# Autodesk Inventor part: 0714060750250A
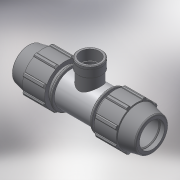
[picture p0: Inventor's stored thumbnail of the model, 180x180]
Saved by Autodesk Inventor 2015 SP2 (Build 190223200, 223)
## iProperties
Created: 2017-02
Part Number: 0714060750250A
Material: Generic
Description: PLASSON TEE WITH THREADED FEMALE OFFTAKE 75-2.1/2"-75
Document SubType Name: Modeling
Designer: KIM
Mass: 92.6774 g
Surface Area: 199.44 cm^2
Volume: 66.1981 cm^3
Density: 1 g/cm^3
Appearance: Default
Author: KIM
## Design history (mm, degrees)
derived "87140.ipt"
feature "Solid1::87140.ipt"
feature "Solid2::87140.ipt"
tag "TaggingFeature1"
body "Solid1"
other parameters: "d2" = 75, "d4" = 13.79167, "d5" = 39.72, "d7" = 134, "d11" = 5.51667, "d13" = 120 deg, "d14" = 97.5, "d15" = 12 deg, "d16" = 116.58, "d18" = 3.75, "d19" = 35 deg, "d20" = 17.5 deg, "d21" = 124.62, "d23" = 0, "d25" = 360 deg, "d27" = 2.68, "d33" = 1.5, "d42" = 59.58, "d43" = 4.02, "d46" = 2.25, "d68" = 9.93, "d72" = 85, "d76" = 72.226, "d80" = 2.16678, "d91" = 100.5, "d93" = 129, "d95" = 67.5, "d112" = 35, "d115" = 90.2825, "d116" = 135 deg, "d117" = 83.0599, "d118" = 331, "d119" = 67.5, "d121" = 0, "d122" = 67.5, "d124" = 0, "d128" = 0, "d129" = 7.5, "d130" = 10.5, "d131" = 0.3, "d132" = 0.3, "d133" = 90.2825, "d_" = 75, "E_" = 134, "A_" = 85, "l_" = 129, "l_2" = 35, "Rp_" = 72.226, "H_" = 331
